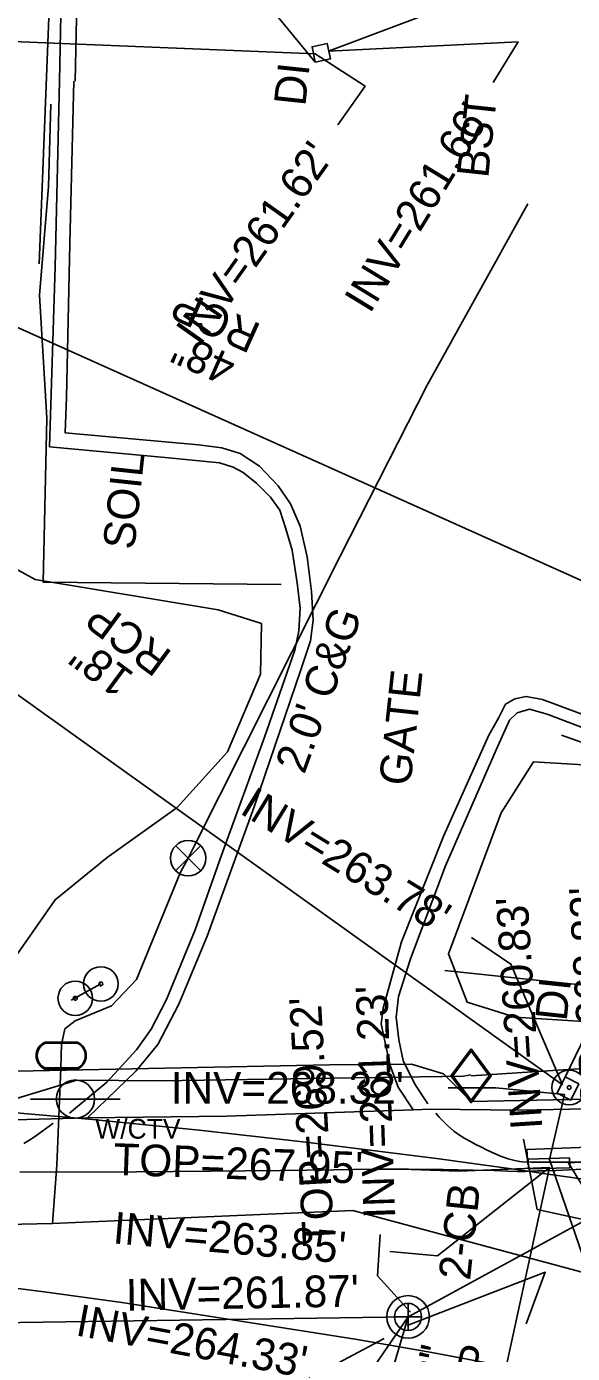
# Model space of a CAD drawing. Extents: x 2100323 to 2109811, y 740376 to 749755.
# Drawn here: x 2105531.2 to 2105600.1, y 742158.5 to 742326 of the extents above; entities that cross this region are included whole.
import ezdxf

# ---------------------------------------------------------------- set-up
doc = ezdxf.new("R2010")
doc.units = 0
for name, color, linetype in [('Exist Horizontal Alignment Direction Label', 7, 'Continuous'), ('Exist Other Culture Fence Line', 7, 'Continuous'), ('Exist Other Culture Gate Text', 7, 'Continuous'), ('Exist Other Culture Located Object CELL', 7, 'Continuous'), ('Exist Other Culture Sign CELL', 7, 'Continuous'), ('Exist Right of Way Line', 7, 'Continuous'), ('Exist Roads Change in Surface', 7, 'Continuous'), ('Exist Roads Curbs', 7, 'Continuous'), ('Exist Roads Curbs Text', 7, 'Continuous'), ('Exist Roads EOP', 7, 'Continuous'), ('Exist Roads EOP Other', 7, 'Continuous'), ('Exist Roads EOP Other Text', 7, 'Continuous'), ('Exist Roads EOT', 7, 'Continuous'), ('Exist Structure Minor Catch Basin', 7, 'Continuous'), ('Exist Structure Minor Catch Basin Text', 7, 'Continuous'), ('Exist Structure Minor Catch Basin Top Elevation', 7, 'Continuous'), ('Exist Structure Minor Drop Inlet', 7, 'Continuous'), ('Exist Structure Minor Drop Inlet Text', 7, 'Continuous'), ('Exist Structure Minor Drop Inlet Top Elevation', 7, 'Continuous'), ('Exist Structure Minor Pipes RCP 15 Inch', 7, 'Continuous'), ('Exist Structure Minor Pipes RCP 15 Inch Invert', 7, 'Continuous'), ('Exist Structure Minor Pipes RCP 15 Inch Leader', 7, 'Continuous'), ('Exist Structure Minor Pipes RCP 18 Inch', 7, 'Continuous'), ('Exist Structure Minor Pipes RCP 18 Inch Invert', 7, 'Continuous'), ('Exist Structure Minor Pipes RCP 18 Inch Leader', 7, 'Continuous'), ('Exist Structure Minor Pipes RCP 18 Inch Text', 7, 'Continuous'), ('Exist Structure Minor Pipes RCP 48 Inch', 7, 'Continuous'), ('Exist Structure Minor Pipes RCP 48 Inch Text', 7, 'Continuous'), ('Exist Utilities Gas UG Line SUE LOS B', 7, 'Continuous'), ('Exist Utilities Gas Valve CELL', 7, 'Continuous'), ('Exist Utilities Sanitary Sewer Manhole CELL', 7, 'Continuous'), ('Exist Utilities Sanitary Sewer Manhole Text', 7, 'Continuous'), ('Exist Utilities Sanitary Sewer UG Line', 7, 'Continuous'), ('Exist Utilities Sanitary Sewer UG Line Invert Elevation', 7, 'Continuous'), ('Exist Utilities Telephone Pole CELL', 7, 'Continuous'), ('Exist Utilities Telephone Pole Cogo Comment', 7, 'Continuous'), ('Exist Utilities Telephone UG Conduit SUE LOS B', 7, 'Continuous'), ('Exist Utilities Water Meter CELL', 7, 'Continuous'), ('Exist Utilities Water UG Line SUE LOS B', 7, 'Continuous'), ('Exist Utilities Water Valve CELL', 7, 'Continuous'), ('Exist Vegetation Woods Line', 7, 'Continuous')]:
    doc.layers.add(name, color=color, linetype=linetype)

msp = doc.modelspace()

# ---------------------------------------------------------------- linework, layer by layer
at = {"layer": 'Exist Horizontal Alignment Direction Label'}
msp.add_line((2105642.46, 742200.58), (2105584.01, 742206.84), dxfattribs=at)
at = {"layer": 'Exist Other Culture Fence Line'}
for points in [[(2105532.84, 742296.01), (2105535.28, 742358.25), (2105552.31, 742464.54)], [(2105598.74, 742236.53), (2105628.53, 742225.99), (2105656.39, 742215.68), (2105671.05, 742239.06), (2105693.86, 742273.76), (2105715.01, 742305.6), (2105736.43, 742338.64), (2105757.27, 742371), (2105783.06, 742409.27), (2105785.25, 742412.99), (2105810.8, 742452.1), (2105819.72, 742465.67)], [(2105534.31, 742316.19), (2105533.99, 742305.77), (2105532.88, 742292.08), (2105533.81, 742276.53), (2105533.32, 742255.85), (2105563.38, 742255.53)]]:
    msp.add_lwpolyline(points, dxfattribs=at)
at = {"layer": 'Exist Other Culture Located Object CELL'}
for radius in [2.18, 0.24]:
    msp.add_circle((2105599.71, 742192.06), radius, dxfattribs=at)
at = {"layer": 'Exist Other Culture Sign CELL'}
msp.add_line((2105540.61, 742205.13), (2105536.88, 742203.07), dxfattribs=at)
for centre, radius in [((2105540.61, 742205.13), 2.18), ((2105537.38, 742203.32), 2.18), ((2105540.61, 742205.13), 0.24), ((2105537.38, 742203.32), 0.24)]:
    msp.add_circle(centre, radius, dxfattribs=at)
at = {"layer": 'Exist Right of Way Line'}
msp.add_arc((2105432.5, 741050.49), 1142.54, 81.05796, 86.49133, dxfattribs=at)
at = {"layer": 'Exist Roads Change in Surface'}
msp.add_lwpolyline([(2105580.01, 742189.22), (2105556.48, 742188.46), (2105538.94, 742188.24)], dxfattribs=at)
at = {"layer": 'Exist Roads Curbs'}
for points in [[(2105535.38, 742319.12), (2105536.16, 742356.48), (2105558.53, 742363.03), (2105560.54, 742364.83), (2105561.86, 742366.4), (2105563.19, 742368.62), (2105565.81, 742377.76)], [(2105536.66, 742188.81), (2105541.35, 742192.74), (2105545.09, 742196.83), (2105546.97, 742199.43), (2105548.89, 742203.17), (2105552.5, 742211.94), (2105555.83, 742221.37), (2105561.27, 742236.28), (2105565.07, 742247.24), (2105565.57, 742249.7), (2105565.76, 742252.56), (2105565.38, 742255.75), (2105564.73, 742259.89), (2105563.96, 742262.59), (2105563.18, 742264.93), (2105562.02, 742266.56), (2105560.31, 742268.31), (2105558.56, 742269.7), (2105557.29, 742270.36), (2105555.56, 742270.91), (2105548.72, 742271.58), (2105534.13, 742272.93), (2105534.84, 742295.63), (2105535.38, 742319.12)], [(2105581.87, 742190.01), (2105580.23, 742192.49), (2105578.74, 742195.46), (2105578.21, 742198.06), (2105577.86, 742200.94), (2105578.18, 742203.56), (2105579.68, 742208.28), (2105584.11, 742220.02), (2105590.51, 742234.68), (2105592.18, 742238.44), (2105593.12, 742239.37), (2105594.69, 742239.83), (2105596.92, 742239.2), (2105624.9, 742228.53), (2105656.03, 742216.57), (2105664.35, 742230.42), (2105670.24, 742239.83)], [(2105602.15, 742182.65), (2105597.83, 742182.63), (2105594.97, 742182.64), (2105593.82, 742182.66), (2105593.47, 742182.71), (2105593.03, 742182.8), (2105592.53, 742182.91), (2105592.02, 742183.05), (2105591.53, 742183.22), (2105591.02, 742183.41), (2105590.48, 742183.64), (2105589.91, 742183.89), (2105589.29, 742184.19), (2105588.63, 742184.52), (2105587.94, 742184.88), (2105587.25, 742185.25), (2105586.55, 742185.63), (2105585.85, 742186.06), (2105585.16, 742186.55), (2105584.34, 742187.25), (2105583.3, 742188.32), (2105582.86, 742188.8)], [(2105534.59, 742187.57), (2105533.27, 742186.59), (2105532.22, 742185.83), (2105531.54, 742185.38), (2105530.9, 742184.98)]]:
    msp.add_lwpolyline(points, dxfattribs=at)
at = {"layer": 'Exist Roads EOP'}
msp.add_lwpolyline([(2105601.47, 742181.73), (2105599.72, 742181.67), (2105598.03, 742181.59), (2105596.7, 742181.55), (2105595.71, 742181.53), (2105594.85, 742181.5), (2105594.1, 742181.47), (2105593.2, 742181.46), (2105591.94, 742181.5), (2105590.22, 742181.57), (2105587.53, 742181.64), (2105583.79, 742181.71), (2105579.44, 742181.75), (2105574.92, 742181.73), (2105570, 742181.66), (2105563.24, 742181.58), (2105554.39, 742181.48), (2105545.12, 742181.4), (2105537.09, 742181.39), (2105530.37, 742181.43)], dxfattribs=at)
at = {"layer": 'Exist Roads EOP Other'}
for points in [[(2105537.38, 742319.08), (2105538.13, 742354.97), (2105559.53, 742361.24), (2105561.97, 742363.43), (2105563.5, 742365.23), (2105565.04, 742367.82), (2105567.74, 742377.25)], [(2105537.19, 742319.08), (2105536.68, 742298.59), (2105536.28, 742279.19), (2105536.09, 742274.71), (2105552.92, 742273.18), (2105555.87, 742272.8), (2105558.18, 742272.09), (2105560.63, 742270.47), (2105562.99, 742267.99), (2105564.53, 742265.74), (2105565.74, 742262.9), (2105566.64, 742259.04), (2105567.18, 742254.67), (2105567.39, 742251.04), (2105567.06, 742248.44), (2105565.85, 742244.78), (2105559.94, 742227.48), (2105554.03, 742211.16), (2105550.44, 742202.57), (2105547.79, 742197.48), (2105545.05, 742194.15), (2105538.94, 742188.24), (2105525.12, 742187.87)], [(2105612.37, 742189.57), (2105593.51, 742189.19), (2105582.23, 742189.31), (2105580.01, 742189.22), (2105578.14, 742192.1), (2105577.1, 742194.83), (2105576.43, 742197.89), (2105575.96, 742200.1), (2105576.25, 742202.06), (2105578.56, 742210.45), (2105583.89, 742223.85), (2105589.56, 742236.53), (2105590.82, 742238.77), (2105591.65, 742240.44), (2105592.86, 742241.11), (2105594.27, 742241.43), (2105596.32, 742241.02), (2105621.3, 742231.73)], [(2105639.55, 742183.25), (2105639.35, 742185.86), (2105621.88, 742185.61), (2105605.14, 742185.45), (2105604.31, 742184.63), (2105594.35, 742184.22), (2105594.5, 742182.34)]]:
    msp.add_lwpolyline(points, dxfattribs=at)
at = {"layer": 'Exist Roads EOT'}
msp.add_lwpolyline([(2105384.01, 742172.54), (2105413.9, 742172.49), (2105424, 742172.51), (2105454.16, 742172.25), (2105463.45, 742172.15), (2105493.96, 742170.82), (2105503.54, 742170.07), (2105533.44, 742166.28), (2105543.26, 742164.9), (2105572.68, 742160.28), (2105581.91, 742158.69), (2105611.48, 742153.13), (2105621.33, 742151.19), (2105650.27, 742144.65), (2105659.07, 742142.59), (2105707.03, 742129.19), (2105716.71, 742126.28), (2105745.75, 742116.8)], dxfattribs=at)
at = {"layer": 'Exist Structure Minor Catch Basin'}
msp.add_lwpolyline([(2105599.74, 742183.17), (2105594.53, 742183.02), (2105594.56, 742181.78), (2105599.77, 742181.93)], close=True, dxfattribs=at)
at = {"layer": 'Exist Structure Minor Catch Basin Top Elevation'}
msp.add_lwpolyline([(2105597.23, 742181.98), (2105585.76, 742181.48), (2105579.77, 742181.7)], dxfattribs=at)
at = {"layer": 'Exist Structure Minor Drop Inlet'}
for points in [[(2105567.67, 742321.49), (2105569.58, 742321.89), (2105569.18, 742323.82), (2105567.27, 742323.42)], [(2105600.94, 742192.53), (2105599.93, 742190.48), (2105598.2, 742191.34), (2105599.21, 742193.39)]]:
    msp.add_lwpolyline(points, close=True, dxfattribs=at)
at = {"layer": 'Exist Structure Minor Drop Inlet Top Elevation'}
for points in [[(2105567.67, 742321.49), (2105559.82, 742331.04), (2105561.49, 742336.81)], [(2105599.16, 742193.27), (2105605.97, 742207.34), (2105611.95, 742207.79)]]:
    msp.add_lwpolyline(points, dxfattribs=at)
at = {"layer": 'Exist Structure Minor Pipes RCP 15 Inch'}
for p, q in [((2105569.35, 742322.87), (2105658.72, 742356.6)), ((2105600.42, 742182.59), (2105599.58, 742182.6))]:
    msp.add_line(p, q, dxfattribs=at)
at = {"layer": 'Exist Structure Minor Pipes RCP 15 Inch Invert'}
msp.add_lwpolyline([(2105599.58, 742182.6), (2105606.63, 742171.1), (2105612.61, 742170.56)], dxfattribs=at)
at = {"layer": 'Exist Structure Minor Pipes RCP 15 Inch Leader'}
msp.add_lwpolyline([(2105569.35, 742322.87), (2105593.26, 742324.03), (2105590.13, 742318.91)], dxfattribs=at)
at = {"layer": 'Exist Structure Minor Pipes RCP 18 Inch'}
for p, q in [((2105507.66, 742324.98), (2105567.66, 742322.55)), ((2105506.49, 742258.54), (2105598.85, 742192.41)), ((2105597.2, 742182.98), (2105599.1, 742191.17)), ((2105589.62, 742147), (2105597.2, 742181.96))]:
    msp.add_line(p, q, dxfattribs=at)
at = {"layer": 'Exist Structure Minor Pipes RCP 18 Inch Leader'}
for points in [[(2105567.66, 742322.55), (2105573.96, 742318.46), (2105570.5, 742313.56)], [(2105598.85, 742192.41), (2105592.36, 742207.63), (2105587.39, 742210.99)], [(2105599.1, 742191.17), (2105590.44, 742192.02), (2105584.44, 742192.02)], [(2105597.2, 742182.98), (2105602.97, 742166.26), (2105608.95, 742165.74)], [(2105597.2, 742181.96), (2105583.07, 742170.82), (2105577.09, 742171.34)]]:
    msp.add_lwpolyline(points, dxfattribs=at)
at = {"layer": 'Exist Structure Minor Pipes RCP 48 Inch'}
msp.add_line((2105506.99, 742298.34), (2105673.08, 742223.83), dxfattribs=at)
at = {"layer": 'Exist Utilities Gas UG Line SUE LOS B'}
msp.add_line((2105586.37, 742193.48), (2105587.31, 742193.65), dxfattribs=at)
for points in [[(2105587.32, 742193.55), (2105616.97, 742195.47), (2105636.73, 742194.06), (2105663.47, 742199.92), (2105723.55, 742175.8), (2105749.21, 742163.19), (2105776.31, 742138.44), (2105797.64, 742126.11), (2105867.62, 742100.96), (2105944.69, 742077.83), (2105983.43, 742072.74), (2106016.46, 742069.93), (2106050.39, 742066.49), (2106059.62, 742066.05)], [(2105525.2, 742189.24), (2105537.56, 742192.98), (2105548.15, 742192.91), (2105586.37, 742193.48)]]:
    msp.add_lwpolyline(points, dxfattribs=at)
at = {"layer": 'Exist Utilities Gas Valve CELL'}
msp.add_line((2105587.32, 742193.55), (2105587.32, 742193.55), dxfattribs=at)
msp.add_lwpolyline([(2105587.32, 742196.96), (2105584.79, 742193.55), (2105587.32, 742190.14), (2105589.86, 742193.55), (2105587.32, 742196.96)], dxfattribs=at)
msp.add_lwpolyline([(2105589.61, 742193.55), (2105587.32, 742196.63), (2105585.03, 742193.55), (2105587.32, 742190.47)], close=True, dxfattribs=at)
at = {"layer": 'Exist Utilities Sanitary Sewer Manhole CELL'}
msp.add_lwpolyline([(2105579.37, 742164.81), (2105579.37, 742161.39), (2105579.37, 742163.1), (2105581.09, 742163.1), (2105577.66, 742163.1)], dxfattribs=at)
for radius in [2.69, 1.71]:
    msp.add_circle((2105579.37, 742163.1), radius, dxfattribs=at)
at = {"layer": 'Exist Utilities Sanitary Sewer UG Line'}
for p, q in [((2105579.38, 742163.1), (2105603.14, 742176.06)), ((2105460.93, 742161.36), (2105579.37, 742163.1)), ((2105579.37, 742163.1), (2105537.86, 742102.65)), ((2105579.37, 742163.1), (2105565.24, 742114.83))]:
    msp.add_line(p, q, dxfattribs=at)
at = {"layer": 'Exist Utilities Sanitary Sewer UG Line Invert Elevation'}
for points in [[(2105601.46, 742175.41), (2105595.67, 742176.68), (2105593.92, 742185.54)], [(2105579.68, 742163.69), (2105575.51, 742168.29), (2105575.84, 742173.51)], [(2105579.24, 742162.01), (2105596.69, 742168.73), (2105594.27, 742162.21)], [(2105576.35, 742160.37), (2105565.3, 742154.47), (2105559.3, 742154.47)]]:
    msp.add_lwpolyline(points, dxfattribs=at)
at = {"layer": 'Exist Utilities Telephone Pole CELL'}
for p, q in [((2105531.73, 742190.6), (2105543.06, 742190.6)), ((2105537.4, 742190.6), (2105537.4, 742190.6))]:
    msp.add_line(p, q, dxfattribs=at)
msp.add_circle((2105537.4, 742190.6), 2.41, dxfattribs=at)
at = {"layer": 'Exist Utilities Telephone UG Conduit SUE LOS B'}
msp.add_lwpolyline([(2105103.13, 742088.49), (2105101.01, 742072.79), (2105111.69, 742081.93), (2105146.14, 742108.41), (2105186.57, 742138.69), (2105209.15, 742157.95), (2105240.68, 742192.75), (2105255.44, 742191.89), (2105405.1, 742191.5), (2105465.37, 742191.7), (2105498.78, 742193.47), (2105569.45, 742194.91), (2105579.79, 742194.99), (2105583.83, 742193.8), (2105587.32, 742190.31), (2105620.45, 742190.95), (2105664.05, 742170.38), (2105679.45, 742164.3), (2105754.9, 742133.71), (2105860.56, 742098.34), (2105944.57, 742073.09)], dxfattribs=at)
at = {"layer": 'Exist Utilities Water Meter CELL'}
msp.add_line((2105535.61, 742196.09), (2105535.61, 742196.09), dxfattribs=at)
for points in [[(2105533.57, 742197.79), (2105537.65, 742197.79)], [(2105533.57, 742197.65), (2105537.65, 742197.65)], [(2105537.65, 742194.52), (2105533.55, 742194.52)], [(2105537.65, 742194.39), (2105533.55, 742194.39)]]:
    msp.add_lwpolyline(points, dxfattribs=at)
for centre, radius, start, end in [((2105534.3, 742196.08), 1.86, 113.178, 245.9794), ((2105534.31, 742196.08), 1.73, 115.3009, 243.7824), ((2105536.9, 742196.09), 1.86, 293.6483, 66.3084), ((2105536.92, 742196.09), 1.73, 295.1272, 64.8728)]:
    msp.add_arc(centre, radius, start, end, dxfattribs=at)
at = {"layer": 'Exist Utilities Water UG Line SUE LOS B'}
for p, q in [((2105535.04, 742182.26), (2105535.55, 742194.49)), ((2105534.52, 742174.88), (2105535.04, 742182.26))]:
    msp.add_line(p, q, dxfattribs=at)
for points in [[(2105552.56, 742222.84), (2105570.82, 742259.14), (2105581.8, 742280.69), (2105594.48, 742303.58)], [(2105550.66, 742219.23), (2105551.63, 742221), (2105552.56, 742222.84)], [(2105535.64, 742197.49), (2105536.08, 742199.48), (2105537.37, 742200.47), (2105541.97, 742202.35), (2105545.12, 742205.71), (2105550.66, 742219.23)], [(2105535.55, 742194.49), (2105535.61, 742196.09), (2105535.64, 742197.49)], [(2105062.44, 742160.92), (2105112.03, 742163.92), (2105142.29, 742165.06), (2105147.9, 742165.55), (2105212.62, 742167.46), (2105233.85, 742168.39), (2105257.67, 742169.36), (2105330.64, 742171.43), (2105371.07, 742171.04), (2105413.23, 742172.03), (2105467.72, 742173.46), (2105534.52, 742174.88), (2105572.4, 742176.52), (2105611.02, 742166.12), (2105614.54, 742164.98), (2105675.34, 742146.61), (2105700.23, 742138.65), (2105717.19, 742133.37), (2105888.1, 742076.65), (2105971.36, 742049.62)]]:
    msp.add_lwpolyline(points, dxfattribs=at)
at = {"layer": 'Exist Utilities Water Valve CELL'}
msp.add_lwpolyline([(2105553.2, 742222.58), (2105550.05, 742219.43), (2105551.63, 742221), (2105553.2, 742219.43), (2105550.05, 742222.58)], dxfattribs=at)
msp.add_circle((2105551.63, 742221), 2.23, dxfattribs=at)
at = {"layer": 'Exist Vegetation Woods Line'}
for points in [[(2105526.58, 742259.28), (2105532.3, 742256.2), (2105555.42, 742252.37), (2105560.87, 742250.62), (2105560.77, 742244.21), (2105556.59, 742234.41), (2105550.22, 742227.38), (2105541.41, 742221.08), (2105534.83, 742215.76), (2105528.9, 742207.24)], [(2105614.18, 742199.58), (2105592.9, 742200.92), (2105586.83, 742202.83), (2105584.47, 742208.91), (2105591.12, 742226.72), (2105595.19, 742233.15), (2105601.49, 742232.77), (2105626.52, 742222.92), (2105643.56, 742215.35), (2105648, 742210.63), (2105646.23, 742205.61), (2105637.28, 742202.05), (2105625.31, 742199.72), (2105614.18, 742199.58)]]:
    msp.add_lwpolyline(points, dxfattribs=at)

# ---------------------------------------------------------------- texts
at = {"layer": 'Exist Other Culture Gate Text'}
msp.add_text('GATE', height=4, rotation=83.8864, dxfattribs=at).set_placement((2105579.67, 742230.04))
at = {"layer": 'Exist Roads Curbs Text'}
msp.add_text('SOIL', height=4, rotation=83.8864, dxfattribs=at).set_placement((2105544.83, 742259.86))
at = {"layer": 'Exist Roads EOP Other Text'}
for s, rotation, p in [('BST', 83.8864, (2105589.48, 742306.77)), ("2.0' C&G", 70.0778, (2105566.28, 742231.49))]:
    msp.add_text(s, height=4, rotation=rotation, dxfattribs=at).set_placement(p)
at = {"layer": 'Exist Structure Minor Catch Basin Text'}
msp.add_text('2-CB', height=4, rotation=83.8864, dxfattribs=at).set_placement((2105587.19, 742167.63))
at = {"layer": 'Exist Structure Minor Catch Basin Top Elevation'}
msp.add_text("TOP=267.95'", height=4, rotation=357.954, dxfattribs=at).set_placement((2105542.13, 742181.04))
at = {"layer": 'Exist Structure Minor Drop Inlet Text'}
for p in [(2105566.41, 742315.84), (2105599.38, 742200.35)]:
    msp.add_text('DI', height=4, rotation=83.8864, dxfattribs=at).set_placement(p)
at = {"layer": 'Exist Structure Minor Pipes RCP 15 Inch Invert'}
msp.add_text("INV=261.66'", height=4, rotation=58.551, dxfattribs=at).set_placement((2105574.56, 742289.62))
at = {"layer": 'Exist Structure Minor Pipes RCP 18 Inch Invert'}
for s, rotation, p in [("INV=261.62'", 54.7374, (2105553.12, 742285.52)), ("INV=263.78'", 328.5872, (2105557.98, 742226.75)), ("INV=263.85'", 355, (2105542.04, 742172.4)), ("INV=264.33'", 349.432, (2105537.29, 742160.8))]:
    msp.add_text(s, height=4, rotation=rotation, dxfattribs=at).set_placement(p)
msp.add_text("INV=268.32'", height=4, dxfattribs=at).set_placement((2105549.43, 742190.02))
at = {"layer": 'Exist Structure Minor Pipes RCP 18 Inch Text'}
for s, rotation, p in [('RCP', 143.5393, (2105549.77, 742246.94)), ('18"', 143.5393, (2105545, 742244.24)), ('18"', 77.7619, (2105583.34, 742151.32)), ('RCP', 77.7619, (2105587.76, 742148.07))]:
    msp.add_text(s, height=4, rotation=rotation, dxfattribs=at).set_placement(p)
at = {"layer": 'Exist Structure Minor Pipes RCP 48 Inch Text'}
for s, p in [('RCP', (2105561.01, 742288.3)), ('48" ', (2105557.95, 742284.19))]:
    msp.add_text(s, height=4, rotation=155.8369, dxfattribs=at).set_placement(p)
at = {"layer": 'Exist Utilities Sanitary Sewer Manhole Text'}
for s, p in [("TOP=268.82'", (2105605.41, 742186.06)), ("TOP=269.52'", (2105570.11, 742172.15))]:
    msp.add_text(s, height=4, rotation=93.1779, dxfattribs=at).set_placement(p)
at = {"layer": 'Exist Utilities Sanitary Sewer UG Line Invert Elevation'}
for s, rotation, p in [("INV=260.83'", 93.689, (2105596.33, 742186.87)), ("INV=261.23'", 91.9737, (2105577.77, 742175.58)), ("INV=261.87'", 1.036, (2105543.79, 742163.89))]:
    msp.add_text(s, height=4, rotation=rotation, dxfattribs=at).set_placement(p)
at = {"layer": 'Exist Utilities Telephone Pole Cogo Comment'}
msp.add_text('W/CTV', height=2.5, dxfattribs=at).set_placement((2105539.9, 742185.6))

doc.saveas('drawing.dxf')
